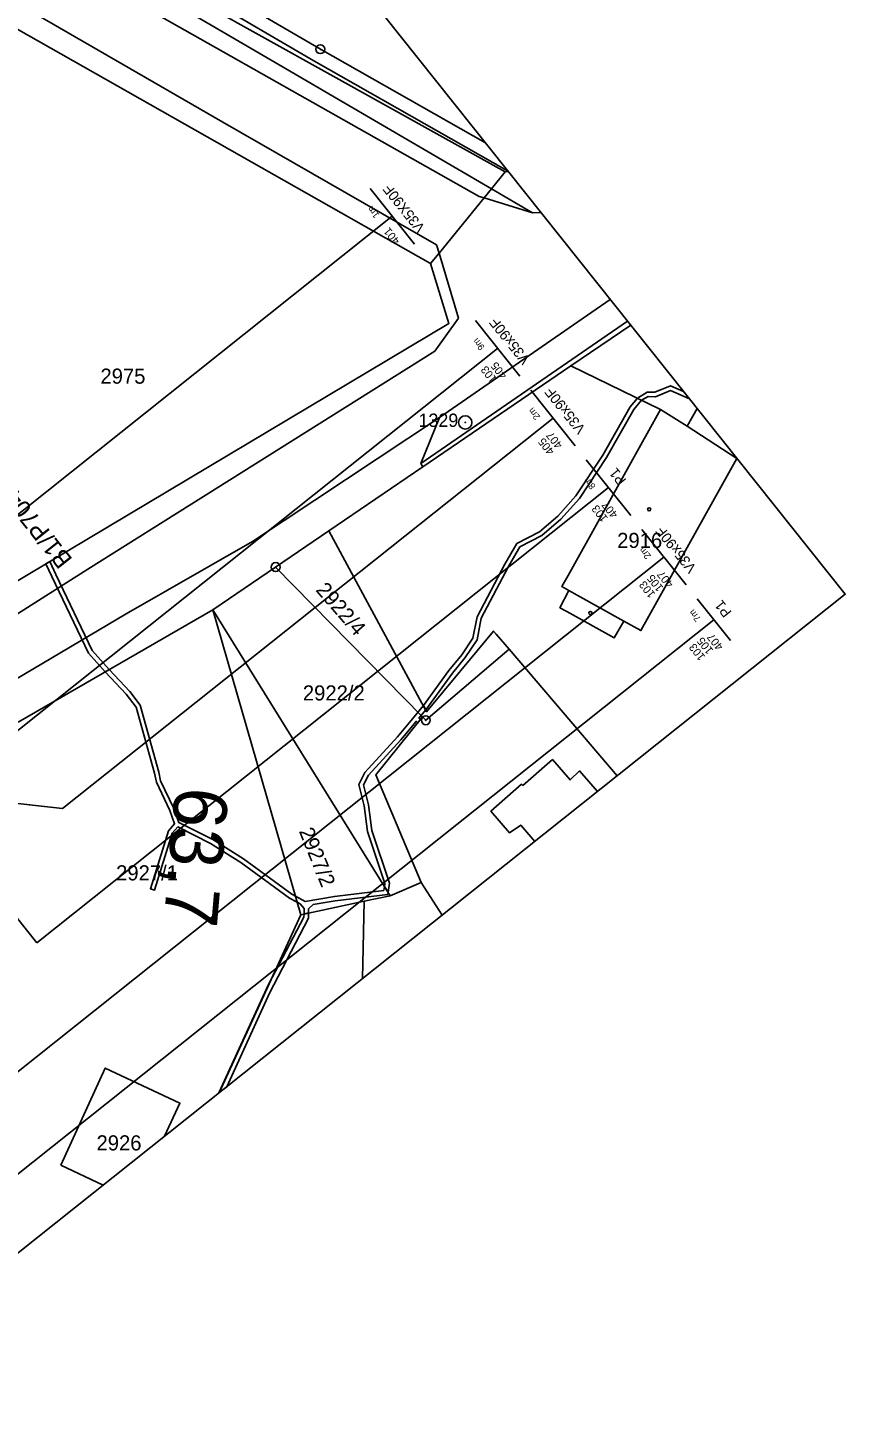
# Model space of a CAD drawing. Extents: x -620412 to -620034, y -1122986 to -1122565.
# Drawn here: x -620126.1 to -620034.3, y -1122986.3 to -1122830 of the extents above; entities that cross this region are included whole.
import ezdxf

# ---------------------------------------------------------------- set-up
doc = ezdxf.new("R2010")
doc.units = 0
for name, color, linetype in [('Hranice parcel', 7, 'Continuous'), ('Parcelní čísla', 7, 'Continuous'), ('Rámečky-tisk', 7, 'Continuous'), ('Vnitřní kresba', 7, 'Continuous'), ('Vrstva 3', 7, 'Continuous'), ('Vrstva 33', 7, 'Continuous'), ('Vrstva 7', 7, 'Continuous'), ('Věcná břemena k části', 7, 'Continuous'), ('Značky bodu BP', 7, 'Continuous'), ('Značky budov', 7, 'Continuous')]:
    doc.layers.add(name, color=color, linetype=linetype)

msp = doc.modelspace()

# ---------------------------------------------------------------- linework, layer by layer
at = {"layer": 'Hranice parcel'}
for p, q in [((-620074.02, -1122848.16), (-620072.47, -1122846.25)), ((-620065.08, -1122868.06), (-620058.37, -1122863.48)), ((-620081.71, -1122879.39), (-620065.08, -1122868.06)), ((-620065.08, -1122868.06), (-620055.03, -1122872.95)), ((-620052.01, -1122874.84), (-620055.03, -1122872.95)), ((-620050.91, -1122872.84), (-620052.01, -1122874.84)), ((-620052.01, -1122874.84), (-620046.45, -1122878.47)), ((-620081.71, -1122879.39), (-620092.29, -1122886.6)), ((-620046.45, -1122878.47), (-620046.41, -1122878.49)), ((-620098.27, -1122890.68), (-620092.29, -1122886.6)), ((-620105.32, -1122895.5), (-620098.27, -1122890.68)), ((-620081.76, -1122907.52), (-620098.27, -1122890.68)), ((-620105.32, -1122895.5), (-620127.22, -1122908.12)), ((-620105.32, -1122895.5), (-620085.4, -1122927.63)), ((-620105.32, -1122895.5), (-620095.45, -1122929.76)), ((-620072.03, -1122899.92), (-620059.88, -1122914.14)), ((-620085.4, -1122927.63), (-620081.92, -1122926.16)), ((-620081.92, -1122926.16), (-620079.54, -1122929.8)), ((-620088.31, -1122928.24), (-620085.4, -1122927.63)), ((-620095.45, -1122929.76), (-620088.31, -1122928.24))]:
    msp.add_line(p, q, dxfattribs=at)
for points in [[(-620072.47, -1122846.25), (-620119.48, -1122820.03), (-620130.17, -1122810.08), (-620136, -1122804.68), (-620136.79, -1122803.52), (-620163.81, -1122763.48)], [(-620074.69, -1122842.98), (-620093.24, -1122832.45), (-620114.36, -1122820.1), (-620123.37, -1122813.77), (-620129.15, -1122808.98), (-620134.98, -1122803.58), (-620147.22, -1122786.5), (-620163.81, -1122763.48)], [(-620074.02, -1122848.16), (-620095.17, -1122835.78), (-620116.57, -1122823.25), (-620125.58, -1122816.92), (-620133.3, -1122810.53), (-620139.43, -1122803.84), (-620150.35, -1122788.75), (-620165.02, -1122768.39), (-620166.09, -1122767.67), (-620166.7, -1122767.69)], [(-620080.86, -1122856.55), (-620132.47, -1122827.27), (-620136.72, -1122822.9), (-620143.18, -1122816.17)], [(-620072.47, -1122846.25), (-620072.14, -1122846.19)], [(-620080.86, -1122856.55), (-620079.9, -1122855.37), (-620074.83, -1122849.15), (-620074.02, -1122848.16)], [(-620074.02, -1122848.16), (-620069.41, -1122850.86), (-620068.46, -1122850.81)], [(-620128.4, -1122892.9), (-620078.79, -1122863.28), (-620080.86, -1122856.55)], [(-620060.67, -1122860.59), (-620064.79, -1122863.44), (-620079.86, -1122873.87), (-620081.95, -1122879.05), (-620081.71, -1122879.39)], [(-620055.03, -1122872.95), (-620065.41, -1122891.61), (-620066.12, -1122892.87), (-620065.34, -1122893.31), (-620066.33, -1122895.25), (-620065.54, -1122895.69), (-620060.23, -1122898.64), (-620059.13, -1122896.76), (-620057.23, -1122897.81), (-620046.45, -1122878.47)], [(-620092.29, -1122886.6), (-620081.3, -1122906.94), (-620073.77, -1122897.87), (-620073.48, -1122898.22), (-620072.03, -1122899.92)], [(-620072.03, -1122899.92), (-620081.39, -1122907.9), (-620081.76, -1122907.52)], [(-620081.76, -1122907.52), (-620087, -1122914.03), (-620081.92, -1122926.16)], [(-620070.5, -1122915.25), (-620067.16, -1122912.32), (-620065.19, -1122914.6), (-620064.13, -1122913.59), (-620062.09, -1122915.91)], [(-620069.14, -1122921.52), (-620070.73, -1122919.69), (-620071.98, -1122920.56), (-620074.07, -1122918.14), (-620070.63, -1122915.1), (-620070.5, -1122915.25)], [(-620088.52, -1122936.96), (-620088.31, -1122928.24)], [(-620095.45, -1122929.76), (-620104.63, -1122949.79)], [(-620110.77, -1122954.68), (-620109.02, -1122950.94), (-620117.41, -1122947.01), (-620122.42, -1122957.94)], [(-620122.42, -1122957.94), (-620117.64, -1122960.16)]]:
    msp.add_lwpolyline(points, dxfattribs=at)
at = {"layer": 'Rámečky-tisk'}
msp.add_lwpolyline([(-620412.11, -1122657.76), (-620150.41, -1122986.26), (-620034.26, -1122893.74), (-620295.96, -1122565.23)], dxfattribs=at)
at = {"layer": 'Vnitřní kresba'}
for p, q in [((-620127.92, -1122819.29), (-620075.39, -1122849.03)), ((-620093.98, -1122833.75), (-620115.22, -1122821.33)), ((-620129.64, -1122825.94), (-620104.21, -1122840.64)), ((-620072.2, -1122846.12), (-620093.98, -1122833.75)), ((-620104.21, -1122840.64), (-620080.18, -1122854.43)), ((-620075.39, -1122849.03), (-620074.83, -1122849.15)), ((-620074.83, -1122849.15), (-620069.41, -1122850.86)), ((-620080.18, -1122854.43), (-620079.9, -1122855.37)), ((-620079.9, -1122855.37), (-620077.73, -1122862.7)), ((-620058.73, -1122863.03), (-620081.95, -1122879.05)), ((-620077.73, -1122862.7), (-620080.37, -1122866.39)), ((-620080.37, -1122866.39), (-620119.37, -1122890.92)), ((-620100.87, -1122887.82), (-620079.86, -1122873.87)), ((-620100.87, -1122887.82), (-620115.07, -1122895.95)), ((-620119.37, -1122890.92), (-620128.12, -1122896.46)), ((-620065.34, -1122893.31), (-620064.4, -1122893.83)), ((-620064.4, -1122893.83), (-620059.13, -1122896.76)), ((-620115.07, -1122895.95), (-620127.59, -1122903.37))]:
    msp.add_line(p, q, dxfattribs=at)
at = {"layer": 'Vrstva 33'}
for p, q in [((-620087.66, -1122848.11), (-620082.67, -1122854.37)), ((-620129.55, -1122886.6), (-620085.16, -1122851.24)), ((-620075.82, -1122862.97), (-620070.83, -1122869.23)), ((-620129.07, -1122910.51), (-620073.32, -1122866.1)), ((-620069.59, -1122870.79), (-620064.6, -1122877.05)), ((-620122.21, -1122917.83), (-620067.09, -1122873.92)), ((-620063.36, -1122878.62), (-620058.37, -1122884.87)), ((-620125.12, -1122932.93), (-620060.86, -1122881.74)), ((-620057.12, -1122886.44), (-620052.14, -1122892.69)), ((-620146.7, -1122962.91), (-620054.63, -1122889.57)), ((-620050.89, -1122894.26), (-620047.15, -1122898.95)), ((-620145.47, -1122973.44), (-620049.02, -1122896.6)), ((-620130.52, -1122916.89), (-620122.21, -1122917.83)), ((-620134.54, -1122921.11), (-620125.12, -1122932.93))]:
    msp.add_line(p, q, dxfattribs=at)
at = {"layer": 'Věcná břemena k části'}
for p, q in [((-620051.77, -1122871.76), (-620052.43, -1122870.93)), ((-620104.64, -1122949.79), (-620103.77, -1122949.11))]:
    msp.add_line(p, q, dxfattribs=at)
for points in [[(-620052.43, -1122870.93), (-620053.9, -1122870.3), (-620055.67, -1122871.02), (-620056.51, -1122871.01), (-620057.61, -1122871.7), (-620058.43, -1122872.68), (-620061.5, -1122878.08), (-620064.52, -1122882.67), (-620066.57, -1122884.95), (-620068.62, -1122886.71), (-620071.17, -1122888.03), (-620072.53, -1122890.37), (-620075.64, -1122896.27), (-620076.12, -1122898.67), (-620077.36, -1122900.56), (-620078.79, -1122902.31), (-620081.67, -1122906.26), (-620081.41, -1122906.74), (-620078.39, -1122902.61), (-620076.96, -1122900.86), (-620075.64, -1122898.87), (-620075.16, -1122896.43), (-620072.09, -1122890.61), (-620070.81, -1122888.41), (-620068.34, -1122887.13), (-620066.22, -1122885.31), (-620064.12, -1122882.97), (-620061.08, -1122878.34), (-620058.01, -1122872.96), (-620057.14, -1122871.92), (-620056.39, -1122871.51), (-620055.57, -1122871.52), (-620053.9, -1122870.84), (-620051.77, -1122871.76)], [(-620103.77, -1122949.11), (-620098.95, -1122938.59), (-620094.59, -1122930.17), (-620094.58, -1122929.57), (-620095.08, -1122929.68), (-620095.09, -1122930.04), (-620099.06, -1122937.63), (-620104.64, -1122949.79)]]:
    msp.add_lwpolyline(points, dxfattribs=at)
for points in [[(-620116.97, -1122902.21), (-620118.88, -1122900.07), (-620122.96, -1122891.51), (-620123.66, -1122890.07), (-620124.09, -1122890.33), (-620123.42, -1122891.73), (-620119.3, -1122900.35), (-620117.41, -1122902.47)], [(-620114.67, -1122904.66), (-620116.97, -1122902.21), (-620117.41, -1122902.47), (-620115.05, -1122904.98), (-620113.96, -1122906.44), (-620111.87, -1122913.85), (-620111.67, -1122914.87), (-620110.16, -1122918.04), (-620109.62, -1122919.54), (-620110.32, -1122920.32), (-620112.35, -1122926.85), (-620111.88, -1122926.99), (-620109.88, -1122920.58), (-620109.27, -1122919.9), (-620105.58, -1122921.76), (-620102.18, -1122923.89), (-620096.7, -1122927.89), (-620095.86, -1122928.36), (-620095.5, -1122928.55), (-620095.06, -1122929.07), (-620095.08, -1122929.68), (-620094.58, -1122929.57), (-620094.56, -1122929.09), (-620094.05, -1122928.61), (-620091.58, -1122928.2), (-620085.68, -1122927.5), (-620085.64, -1122927.24), (-620086.05, -1122926.58), (-620086.12, -1122927.04), (-620091.66, -1122927.7), (-620094.97, -1122928.27), (-620096.05, -1122927.68), (-620096.44, -1122927.47), (-620101.9, -1122923.47), (-620105.34, -1122921.32), (-620109.13, -1122919.41), (-620109.7, -1122917.84), (-620111.19, -1122914.71), (-620111.39, -1122913.73), (-620113.5, -1122906.22)], [(-620081.41, -1122906.74), (-620081.67, -1122906.26), (-620082.7, -1122907.53), (-620084.59, -1122909.76), (-620088.25, -1122913.79), (-620088.93, -1122915.11), (-620088.33, -1122917.52), (-620087.94, -1122920.4), (-620086, -1122926.24), (-620086.05, -1122926.58), (-620085.64, -1122927.24), (-620085.48, -1122926.2), (-620087.45, -1122920.28), (-620087.83, -1122917.42), (-620088.4, -1122915.17), (-620087.83, -1122914.07), (-620084.21, -1122910.09), (-620082.48, -1122908.04), (-620082.3, -1122908.18), (-620081.99, -1122907.79), (-620082.16, -1122907.66)]]:
    msp.add_lwpolyline(points, close=True, dxfattribs=at)
at = {"layer": 'Značky bodu BP'}
for centre, radius in [((-620093.24, -1122832.45), 0.5), ((-620093.24, -1122832.45), 0.0303), ((-620076.96, -1122874.42), 0.75), ((-620076.96, -1122874.42), 0.03), ((-620098.27, -1122890.68), 0.5), ((-620098.27, -1122890.68), 0.0303), ((-620081.39, -1122907.9), 0.5), ((-620081.39, -1122907.9), 0.0303)]:
    msp.add_circle(centre, radius, dxfattribs=at)
at = {"layer": 'Značky budov'}
for centre in [(-620056.29, -1122884.18), (-620062.9, -1122895.84)]:
    msp.add_circle(centre, 0.175, dxfattribs=at)

# ---------------------------------------------------------------- texts
at = {"layer": 'Parcelní čísla'}
for s, p in [('2975', (-620117.96, -1122870.06)), ('2916', (-620059.89, -1122888.53)), ('2922/2', (-620095.21, -1122905.68)), ('2927/1', (-620116.2, -1122925.91)), ('2926', (-620118.4, -1122956.27))]:
    msp.add_text(s, height=1.7, dxfattribs=at).set_placement(p)
for s, rotation, p in [('2922/4', 311, (-620093.84, -1122893.3)), ('2927/2', 292, (-620095.68, -1122920.36))]:
    msp.add_text(s, height=1.7, rotation=rotation, dxfattribs=at).set_placement(p)
at = {"layer": 'Vrstva 3'}
msp.add_text('B1/P7048', height=2, rotation=128.542, dxfattribs=at).set_placement((-620121.02, -1122889.81))
at = {"layer": 'Vrstva 33'}
for s, height, p in [('V35X90F', 1.15, (-620081.41, -1122852.51)), ('1m', 0.75, (-620086.57, -1122851.08)), ('401', 0.9, (-620084.26, -1122853.98)), ('V35x90F', 1.15, (-620069.61, -1122867.31)), ('9m', 0.75, (-620074.73, -1122865.94)), ('103', 0.9, (-620073.34, -1122869.53)), ('405', 0.9, (-620072.22, -1122869.09)), ('V35x90F', 1.15, (-620063.38, -1122875.13)), ('2m', 0.75, (-620068.5, -1122873.76)), ('405', 0.9, (-620066.89, -1122877.63)), ('407', 0.9, (-620065.98, -1122876.93)), ('P1', 1.15, (-620058.8, -1122880.89)), ('8m', 0.75, (-620062.27, -1122881.58)), ('103', 0.9, (-620060.88, -1122885.17)), ('407', 0.9, (-620059.75, -1122884.75)), ('V35x90F', 1.15, (-620050.92, -1122890.77)), ('2m', 0.75, (-620056.04, -1122889.41)), ('105', 0.9, (-620054.65, -1122892.99)), ('407', 0.9, (-620053.52, -1122892.57)), ('103', 0.9, (-620055.55, -1122893.71)), ('P1', 1.15, (-620046.96, -1122895.75)), ('7m', 0.75, (-620050.43, -1122896.45)), ('407', 0.9, (-620047.91, -1122899.61)), ('103', 0.9, (-620049.94, -1122900.75)), ('105', 0.9, (-620049.04, -1122900.03))]:
    msp.add_text(s, height=height, rotation=128.542, dxfattribs=at).set_placement(p)
at = {"layer": 'Vrstva 7'}
msp.add_text('63,7', height=6, rotation=265.1213, dxfattribs=at).set_placement((-620109.54, -1122915.27))
at = {"layer": 'Značky bodu BP'}
msp.add_text('1329', height=1.5, dxfattribs=at).set_placement((-620082.21, -1122874.92))

doc.saveas('drawing.dxf')
